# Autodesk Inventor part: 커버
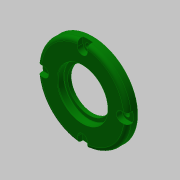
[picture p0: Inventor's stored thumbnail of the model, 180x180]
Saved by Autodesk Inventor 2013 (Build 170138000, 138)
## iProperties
Created: 2019-05
Part Number: 커버
Material: 알루미늄 6061
Document SubType Name: Modeling
Designer: mduedu
Density: 1 g/cm^3
Author: mduedu
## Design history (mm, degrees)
sketch "스케치1"
  geometry: L1 (0, 0)-(36, 0); L2 (36, 0)-(36, -8); L3 (36, -8)-(0, -8); L4 (0, -8)-(0, 0); L5 (0, -8)-(26, -8); L6 (26, -8)-(26, -12); L7 (26, -12)-(0, -12); L8 (0, -12)-(0, -8)
  constraints: 16 end point, 4 parallel, 2 horizontal, 2 perpendicular
  dimensions: "d0" = 72 diameter of L2 L4; "d2" = 52 diameter of L6 L8; "d3" = 12 distance between parallel lines of L7 L1; "d4" = 4 distance between parallel lines of L7 L3
revolve "회전1" sketch "스케치1" stored, may be unused: angle "d5" = 90 deg
sketch "스케치2" dims "d6" = 62
  geometry: L1 (-4, 31)-(-4, 35.777); L2 (4, 31)-(4, 35.777); A1 r 4 centre (0, 31) between (-4, 31) and (4, 31); A2 r 36 centre (0, 0) between (-4, 35.777) and (4, 35.777) reference; A3 r 36 centre (0, 0) between (4, 35.777) and (-4, 35.777); 2 further points
  constraints: 6 point on circle, 4 end point, 2 centre point, 2 coincident, 2 tangent, 2 vertical alignment, 1 parallel, 1 vertical, 2 other
  dimensions: "d7" = 8 distance between parallel lines of L2 L1
extrude "돌출1" cut sketch "스케치2" distance "d8" = 4.4; taper "d9" = 0 deg
fillet "모깎기1" dims "d13" = 3
sketch "스케치3"
  geometry: L1 (36, -4.4)-(36, -8) reference; L2 (36, -8)-(26, -8) reference; L3 (26, -8)-(26, -12) reference; L4 (26, -12)-(-26, -12) reference; L5 (-26, -12)-(-26, -8) reference; L6 (-26, -8)-(-36, -8) reference; L7 (-36, -8)-(-36, -4.4) reference; L8 (-36, -4.4)-(-27, -4.4) reference; L9 (-27, -4.4)-(-27, 0) reference; L10 (-27, 0)-(27, 0) reference; L11 (27, 0)-(27, -4.4) reference; L12 (27, -4.4)-(36, -4.4) reference; L13 (0, 0)-(20, 0); L14 (20, 0)-(20, -5.2); L15 (20, -5.2)-(0, -5.2); L16 (0, -5.2)-(0, 0); L17 (0, -5.2)-(17, -5.2); L18 (17, -5.2)-(17, -8); L19 (17, -8)-(0, -8); L20 (0, -8)-(0, -5.2); L21 (0, -8)-(23, -8); L22 (23, -8)-(23, -12); L23 (23, -12)-(0, -12); L24 (0, -12)-(0, -8)
  constraints: 24 end point, 6 parallel, 3 horizontal, 3 perpendicular, 1 point on line
  dimensions: "d14" = 40 diameter of L14 L16; "d16" = 5.2 distance of L13.end L14.end; "d17" = 46 diameter of L22 L24; "d18" = 4 distance of L21.end L22.end; "d19" = 34 diameter of L18 L20
revolve "회전2" sketch "스케치3" stored, may be unused: angle "d20" = 90 deg
chamfer "모따기1" distance "d21" = 0.5; stored, may be unused: second distance "d22" = 2, angle "d23" = 30 deg
fillet "모깎기2" dims "d24" = 0.2
fillet "모깎기3" dims "d25" = 3
chamfer "모따기2" distance "d26" = 1; stored, may be unused: second distance "d27" = 2, angle "d28" = 30 deg
sketch "스케치4" dims "d29" = 62
  geometry: 6 further points
  constraints: 2 vertical alignment, 1 coincident, 7 other
  dimensions: "d32" = 360 deg dimension on point (0, 0) point (0, 31) (derived)
sketch "스케치5"
  geometry: 4 further points
  constraints: 4 other
hole "구멍1" sketch "스케치5" at (-31, 0), (0, -31), (31, 0), (0, 31) diameter "d34" = 4.5; stored, may be unused: countersink angle "d38" = 90 deg, drill point angle "d40" = 0 deg; dims "d35" = 6, "d36" = 4, "d37" = 2, "d39" = 8
node "솔리드1"
pattern_circular "원형 패턴1" dims angle "d11" = 360 deg
node "절단 모서리 투영1"
